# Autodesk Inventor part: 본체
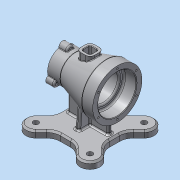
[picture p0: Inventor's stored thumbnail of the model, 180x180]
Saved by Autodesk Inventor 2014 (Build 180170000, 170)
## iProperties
Created: 2018-03
Part Number: 본체
Material: 알루미늄 6061
Document SubType Name: Modeling
Designer: kb542
Density: 2.71 g/cm^3
Appearance: 알루미늄 - 평지
Mass: 1014.96 g
Surface Area: 853.96 cm^2
Volume: 374.523 cm^3
Author: kb542
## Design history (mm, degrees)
sketch "스케치1"
  geometry: L1 (-45, -45)-(45, -45); L2 (45, -45)-(45, 45); L3 (45, 45)-(-45, 45); L4 (-45, 45)-(-45, -45); L5 (-45, -45)-(45, 45); L6 (45, -45)-(-45, 45); 1 further point
  constraints: 12 end point, 2 midpoint, 2 parallel, 1 horizontal, 1 perpendicular
  dimensions: "d0" = 90 distance of L2.end L3.end; "d1" = 90 distance of L1.end L2.end
extrude "돌출1" new body sketch "스케치1" distance "d2" = 12; taper "d3" = 0 deg
sketch "스케치2"
  geometry: L1 (-45, 45)-(-45, -45) reference; L2 (-45, -45)-(45, -45) reference; L3 (0, 0)-(-59.607, -59.607); L4 (0, 0)-(-45, 0); L5 (-62.225, -36.77)-(-41.012, -15.556); L6 (-36.77, -62.225)-(-15.556, -41.012); L7 (-15.556, -41.012)-(-41.012, -15.556); A1 r 70 centre (0, 0) between (-49.497, -49.497) and (-60.483, -35.239); A2 r 18 centre (-49.497, -49.497) between (-60.483, -35.239) and (-36.77, -62.225); 1 further point
  constraints: 10 end point, 5 point on circle, 2 centre point, 2 symmetric about line, 1 coincident, 1 midpoint, 1 parallel, 1 perpendicular, 1 point on line, 1 tangent
  dimensions: "d4" = 140 diameter of A1; "d5" = 45 deg angle of L4 L3; "d6" = 36 diameter of A2; "d8" = 40 distance from line of point (0, 0) L7
extrude "돌출2" join sketch "스케치2" distance "d9" = 12; taper "d10" = 0 deg
sketch "스케치3"
  geometry: L1 (-19.544, 0)-(19.544, 0) reference; L2 (-67.497, 12)-(-67.497, 0) reference; L3 (-30, 82)-(-30, 127); L4 (-30, 127)-(-50, 127); L5 (-50, 127)-(-50, 82); L6 (-50, 82)-(50, 82); L7 (50, 109.5)-(50, 82); L8 (67.497, 0)-(36.77, 0) reference; L9 (50, 109.5)-(27, 109.5); L10 (27, 109.5)-(-30, 127); 6 further points
  constraints: 14 end point, 4 midpoint, 2 parallel, 1 horizontal, 1 perpendicular, 1 point on line, 1 vertical alignment
  dimensions: "d24" = 20 distance of L3.end L4.end; "d26" = 82 distance from line of L8 L6.end; "d27" = 100 distance between parallel lines of L7 L5; "d30" = 90 diameter of L4 L6; "d42" = 77 distance from line of L5 L9.end; "d43" = 55 diameter of L9 L6
revolve "회전1" sketch "스케치3" stored, may be unused: angle "d34" = 90 deg
sketch "스케치4"
  geometry: L1 (-50, 37)-(-50, 127) reference; L2 (-50, 82)-(-27, 82); L3 (-27, 82)-(-27, 117); L4 (-27, 117)-(-50, 117); L5 (-50, 117)-(-50, 82); L6 (-27, 82)-(20, 82); L7 (20, 82)-(20, 108); L8 (20, 108)-(-27, 108); L9 (-27, 108)-(-27, 82); L10 (20, 82)-(50, 82); L11 (50, 82)-(50, 102); L12 (50, 102)-(20, 102); L13 (20, 102)-(20, 82); L14 (50, 54.5)-(50, 109.5) reference; 1 further point
  constraints: 24 end point, 6 parallel, 3 horizontal, 3 perpendicular, 1 midpoint
  dimensions: "d35" = 23 distance of L3.end L4.end; "d36" = 30 distance of L11.end L12.end; "d37" = 47 distance of L7.end L8.end; "d38" = 52 diameter of L8 L6; "d39" = 70 diameter of L4 L2; "d41" = 40 diameter of L12 L10
revolve "회전2" sketch "스케치4" stored, may be unused: angle "d44" = 90 deg
sketch "스케치5"
  geometry: L1 (4, 24)-(-4, 24); L2 (-4, 24)-(-4, -24); L3 (-4, -24)-(4, -24); L4 (4, -24)-(4, 24); L5 (4, 24)-(-4, -24); L6 (-4, 24)-(4, -24); L7 (37, 4)-(-37, 4); L8 (-37, 4)-(-37, -4); L9 (-37, -4)-(37, -4); L10 (37, -4)-(37, 4); L11 (37, 4)-(-37, -4); L12 (-37, 4)-(37, -4); 1 further point
  constraints: 24 end point, 4 midpoint, 4 parallel, 2 horizontal, 2 perpendicular
  dimensions: "d45" = 48 distance of L1.end L2.end; "d46" = 8 distance of L2.end L3.end; "d47" = 8 distance of L9.end L7.start; "d48" = 74 distance of L8.end L9.end
extrude "돌출3" join sketch "스케치5" stored distance "d49" = 12; taper "d50" = 0 deg
extrude "돌출4" join sketch "스케치5" stored distance "d51" = 12; taper "d52" = 0 deg
feature "면 기울기1" dims angle "d53" = 5 deg
node "작업 평면1"
sketch "스케치6"
  geometry: L1 (-12.5, 12.5)-(12.5, 12.5); L2 (12.5, 12.5)-(12.5, -12.5); L3 (12.5, -12.5)-(-12.5, -12.5); L4 (-12.5, -12.5)-(-12.5, 12.5); L5 (-12.5, 12.5)-(12.5, -12.5); L6 (12.5, 12.5)-(-12.5, -12.5); L7 (-7.5, 7.5)-(7.5, 7.5); L8 (7.5, 7.5)-(7.5, -7.5); L9 (7.5, -7.5)-(-7.5, -7.5); L10 (-7.5, -7.5)-(-7.5, 7.5); L11 (-7.5, 7.5)-(7.5, -7.5); L12 (7.5, 7.5)-(-7.5, -7.5); 1 further point
  constraints: 24 end point, 4 midpoint, 4 parallel, 2 horizontal, 2 perpendicular, 1 point on line
  dimensions: "d55" = 25 distance of L2.end L3.end; "d56" = 25 distance of L3.end L1.start (= d55); "d57" = 15 distance of L8.end L9.end
extrude "돌출5" join sketch "스케치6" stored distance "d58" = 12; taper "d59" = 0 deg
extrude "돌출6" cut sketch "스케치6" stored distance "d60" = 12; taper "d61" = 0 deg
sketch "스케치7"
  geometry: A1 r 18 centre (-49.497, 49.497) between (-36.77, 62.225) and (-62.225, 36.77) reference; A2 r 18 centre (-49.497, -49.497) between (-62.225, -36.77) and (-36.77, -62.225) reference; A3 r 18 centre (49.497, -49.497) between (36.77, -62.225) and (62.225, -36.77) reference; A4 r 18 centre (49.497, 49.497) between (62.225, 36.77) and (36.77, 62.225) reference; 1 further point
hole "구멍1" sketch "스케치7" at (-49.497, 49.497), (49.497, 49.497), (49.497, -49.497), (-49.497, -49.497) diameter "d62" = 10; stored, may be unused: countersink angle "d66" = 90 deg, drill point angle "d68" = 118 deg; dims "d63" = 6, "d64" = 4, "d65" = 2, "d67" = 8
fillet "모깎기1" dims "d69" = 25
chamfer "모따기1" distance "d70" = 3; stored, may be unused: second distance "d71" = 2, angle "d72" = 45 deg
fillet "모깎기2" dims "d73" = 8
fillet "모깎기3" dims "d74" = 1
fillet "모깎기4" dims "d75" = 3
fillet "모깎기5" dims "d76" = 3
chamfer "모따기2" distance "d77" = 1; stored, may be unused: second distance "d78" = 2, angle "d79" = 45 deg
sketch "스케치8"
  geometry: C1 r 20 at (0, 0) reference; C2 r 7 at (27.5, 0); 2 further points
  constraints: 2 horizontal alignment, 1 centre point, 1 other
  dimensions: "d80" = 14 diameter of C2
extrude "돌출7" join sketch "스케치8" distance "d81" = 15; taper "d82" = 0 deg
fillet "모깎기6" dims "d83" = 3
fillet "모깎기7" dims "d84" = 1
sketch "스케치9"
  geometry: A1 r 7 centre (-41.25, -23.816) between (-47.248, -20.206) and (-35.125, -27.205) reference; A2 r 7 centre (0, 0) between (-0.127, -6.999) and (-0.127, 6.999) reference; A3 r 7 centre (-41.25, 23.816) between (-35.125, 27.205) and (-47.248, 20.206) reference; 1 further point
hole "구멍2" sketch "스케치9" at (0, 0), (-41.25, 23.816), (-41.25, -23.816) diameter "d88" = 3.242; stored, may be unused: countersink angle "d92" = 90 deg, drill point angle "d94" = 118 deg; dims "d89" = 9, "d90" = 4, "d91" = 2, "d93" = 11
fillet "모깎기8" dims "d95" = 3
fillet "모깎기9" dims "d96" = 3
sketch "스케치10" dims "d97" = 80
  geometry: C1 r 35 at (0, 0) reference; C2 r 45 at (0, 0) reference; 3 further points
  constraints: 2 horizontal alignment, 1 coincident, 2 other
hole "구멍3" sketch "스케치10" at (-40, 0) diameter "d98" = 3.242; stored, may be unused: countersink angle "d102" = 90 deg, drill point angle "d104" = 118 deg; dims "d99" = 9, "d100" = 4, "d101" = 2, "d103" = 11
node "작업 평면2"
sketch "스케치11"
  geometry: L1 (45, -9.189)-(45, 9.189) reference; 2 further points
  constraints: 1 other
  dimensions: "d115" = 45 distance from line of L1 point (0, 35); "d116" = 35 distance of point (0, 0) point (0, 35)
feature "엠보싱1" sketch "스케치11" dims "d9" = 12, "d109" = 0.5, "d110" = 0
fillet "모깎기10" dims "d111" = 3
chamfer "모따기3" distance "d112" = 1; stored, may be unused: second distance "d113" = 2, angle "d114" = 45 deg
node "솔리드1"
mirror "대칭1"
mirror "대칭2"
pattern_circular "원형 패턴1" dims "d86" = 360 deg
pattern_circular "원형 패턴2" dims angle "d106" = 360 deg
other parameters: "d54" = -127, "d108" = 5
